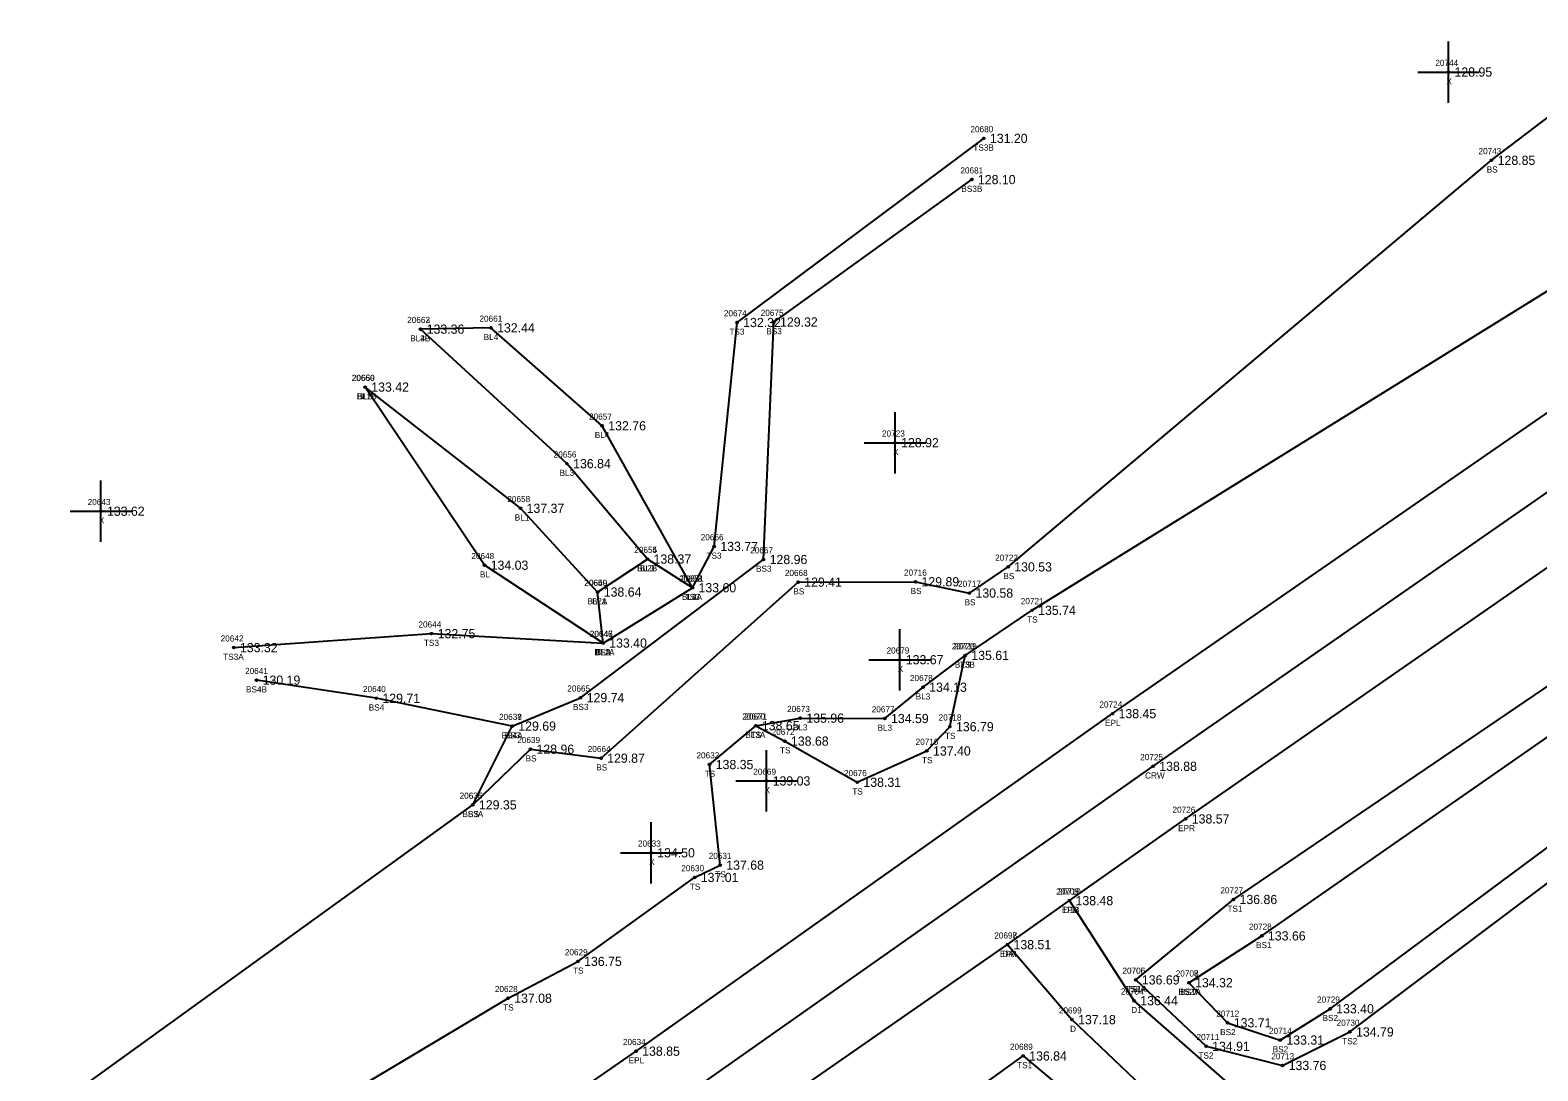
# Model space of a CAD drawing. Extents: x 2449605 to 2452431, y 1012876 to 1014922.
# Drawn here: x 2451655.9 to 2451901.5, y 1014436.4 to 1014606 of the extents above; entities that cross this region are included whole.
import ezdxf

# ---------------------------------------------------------------- set-up
doc = ezdxf.new("R2010")
doc.units = 0
for name, color, linetype in [('RD_DTM_BkLn1', 7, 'Continuous'), ('RD_DTM_BkLn2', 7, 'Continuous'), ('RD_DTM_BkLn_txCode', 7, 'Continuous'), ('RD_EX_Driveway', 7, 'Continuous'), ('RD_EX_Driveway_txCode', 7, 'Continuous'), ('RD_EX_Misc', 7, 'Continuous'), ('RD_EX_Misc_txCode', 7, 'Continuous'), ('RD_EX_Road', 7, 'Continuous'), ('RD_EX_Road_txCode', 7, 'Continuous'), ('RD_EX_TX_Driveway_ELEV', 7, 'Continuous'), ('RD_EX_TX_Misc_ELEV', 7, 'Continuous'), ('RD_EX_TX_Road_ELEV', 7, 'Continuous'), ('RD_HC_Survey_ELEV', 7, 'Continuous'), ('RD_HC_Survey_txCode', 7, 'Continuous'), ('RD_SMD_Locator', 7, 'Continuous')]:
    doc.layers.add(name, color=color, linetype=linetype)

msp = doc.modelspace()

# ---------------------------------------------------------------- linework, layer by layer
at = {"layer": 'RD_DTM_BkLn1'}
msp.add_line((2451748.31, 1014514.42), (2451756.42, 1014519.79), dxfattribs=at)
for points in [[(2451118.89, 1013985.11), (2451203.66, 1014044.04), (2451282.83, 1014099.78), (2451359.44, 1014152.74), (2451440.83, 1014209.36), (2451521.56, 1014265.18), (2451601.57, 1014320.62), (2451681.76, 1014376.26), (2451760.87, 1014431.18), (2451838.81, 1014486.02), (2451917.14, 1014540.46), (2451997.53, 1014596.52), (2452078.1, 1014652.75), (2452159.13, 1014709.2), (2452240.28, 1014765.75), (2452322.88, 1014822.76), (2452350.66, 1014841.92)], [(2451763.75, 1014515.12), (2451749.05, 1014541.51), (2451730.94, 1014557.47), (2451719.46, 1014557.26)], [(2451763.75, 1014515.12), (2451756.42, 1014519.79), (2451743.32, 1014535.34), (2451719.46, 1014557.26)], [(2451749.2, 1014506.11), (2451729.89, 1014518.79), (2451710.44, 1014547.82)], [(2451749.2, 1014506.11), (2451748.31, 1014514.42), (2451735.74, 1014528.07), (2451710.44, 1014547.82)], [(2451774.07, 1014492.64), (2451781.32, 1014493.87), (2451795.11, 1014493.81), (2451801.33, 1014498.91), (2451808.19, 1014504.09)]]:
    msp.add_lwpolyline(points, dxfattribs=at)
at = {"layer": 'RD_DTM_BkLn2'}
for points in [[(2451646.62, 1014421.01), (2451727.98, 1014479.74), (2451737.36, 1014488.81), (2451748.87, 1014487.34), (2451780.97, 1014516.03), (2451800.08, 1014516.09), (2451808.87, 1014514.25), (2451815.19, 1014518.52), (2451893.94, 1014584.77), (2451968.95, 1014641.82), (2452055.92, 1014696.27), (2452133.42, 1014744.91), (2452217.68, 1014799.33), (2452300.38, 1014857.1), (2452325.49, 1014877.68)], [(2451585.42, 1014345.19), (2451660.13, 1014404.28), (2451733.72, 1014448.23), (2451745.11, 1014454.23), (2451764.12, 1014467.91), (2451768.27, 1014469.92), (2451766.55, 1014486.31), (2451774.07, 1014492.64), (2451778.81, 1014490.13), (2451790.61, 1014483.42), (2451801.96, 1014488.52), (2451805.7, 1014492.48), (2451808.19, 1014504.09), (2451819.08, 1014511.44), (2451904.04, 1014564.11), (2451984.51, 1014617.35), (2452065.76, 1014673.28), (2452142.48, 1014732.95), (2452225.73, 1014787.51), (2452309.72, 1014842.9), (2452337.15, 1014861.43)], [(2451835.98, 1014451.22), (2451851.89, 1014464.32), (2451932.21, 1014518.85), (2452011.75, 1014575.42), (2452092.83, 1014631.63), (2452174.74, 1014689.14), (2452254.45, 1014747.21), (2452337.17, 1014802.96), (2452364.31, 1014821.77)], [(2451844.65, 1014450.76), (2451856.52, 1014458.39), (2451935.8, 1014513.56), (2452015.2, 1014570.69), (2452096.12, 1014626.95), (2452178.85, 1014683.69), (2452258.49, 1014741.29), (2452341.42, 1014797.77), (2452367.36, 1014815.99)], [(2451844.65, 1014450.76), (2451850.95, 1014444.22), (2451859.52, 1014441.41), (2451867.64, 1014446.51), (2451943.4, 1014502.76), (2452022.93, 1014557.31), (2452109.2, 1014611.97), (2452189.91, 1014668.61), (2452268.85, 1014723.73), (2452349.37, 1014785.51), (2452374.28, 1014800.27)], [(2451835.98, 1014451.22), (2451847.43, 1014440.4), (2451859.89, 1014437.27), (2451870.87, 1014442.74), (2451946.09, 1014499.37), (2452026.47, 1014553.48), (2452112.39, 1014607.71), (2452192.56, 1014666.03), (2452272.86, 1014720.14), (2452352.28, 1014781.04), (2452376.77, 1014796.76)], [(2451689.04, 1014505.36), (2451721.26, 1014507.64), (2451749.2, 1014506.11), (2451763.75, 1014515.12), (2451767.3, 1014521.85), (2451771.03, 1014558.34), (2451811.23, 1014588.35)], [(2451727.98, 1014479.74), (2451734.39, 1014492.57), (2451745.53, 1014497.2), (2451775.34, 1014519.72), (2451777.03, 1014558.42), (2451809.27, 1014581.63)], [(2451734.39, 1014492.57), (2451712.26, 1014497.11), (2451692.74, 1014500.06)], [(2451122.2, 1013975.67), (2451126.64, 1013971.77), (2451133.91, 1013974.2), (2451213.29, 1014028.58), (2451297.97, 1014080.75), (2451370.59, 1014133.41), (2451455.73, 1014187.81), (2451537.96, 1014241.24), (2451616.44, 1014298.53), (2451698.16, 1014354.19), (2451775.09, 1014408.12), (2451817.62, 1014438.82), (2451833.1, 1014425.86), (2451826.37, 1014414.29)]]:
    msp.add_lwpolyline(points, dxfattribs=at)
at = {"layer": 'RD_EX_Driveway'}
for points in [[(2451893.48, 1014396.37), (2451856.56, 1014429.54), (2451835.71, 1014447.82), (2451825.17, 1014464.13)], [(2451815.07, 1014456.96), (2451825.59, 1014444.74), (2451854.09, 1014417.6), (2451886.88, 1014382.9)]]:
    msp.add_lwpolyline(points, dxfattribs=at)
at = {"layer": 'RD_EX_Misc'}
for p, q in [((2451886.91, 1014594.15), (2451886.91, 1014604.15)), ((2451881.91, 1014599.15), (2451891.91, 1014599.15)), ((2451796.76, 1014533.75), (2451796.76, 1014543.75)), ((2451791.76, 1014538.75), (2451801.76, 1014538.75)), ((2451667.38, 1014522.59), (2451667.38, 1014532.59)), ((2451662.38, 1014527.59), (2451672.38, 1014527.59)), ((2451797.52, 1014498.39), (2451797.52, 1014508.39)), ((2451792.52, 1014503.39), (2451802.52, 1014503.39)), ((2451775.83, 1014478.64), (2451775.83, 1014488.64)), ((2451770.83, 1014483.64), (2451780.83, 1014483.64)), ((2451757.02, 1014466.93), (2451757.02, 1014476.93)), ((2451752.02, 1014471.93), (2451762.02, 1014471.93))]:
    msp.add_line(p, q, dxfattribs=at)
at = {"layer": 'RD_EX_Road'}
for points in [[(2451113.37, 1013993.22), (2451114.95, 1013995.06), (2451198.45, 1014053.46), (2451277.07, 1014108.71), (2451354.65, 1014162.03), (2451438.1, 1014219.98), (2451516.17, 1014274.12), (2451595.76, 1014329.36), (2451675.91, 1014385.09), (2451754.57, 1014439.6), (2451832.18, 1014494.6), (2451911.27, 1014549.31), (2451991.99, 1014605.1), (2452071.96, 1014661.47), (2452153.31, 1014717.5), (2452234.82, 1014774.14), (2452317.24, 1014831.48), (2452344.94, 1014850.58)], [(2451124.98, 1013977.04), (2451208.96, 1014035.6), (2451289.19, 1014091.86), (2451364.64, 1014143.97), (2451446.58, 1014201.16), (2451526.53, 1014256.42), (2451607.39, 1014312.42), (2451687.4, 1014368.14), (2451765.64, 1014422.59), (2451815.07, 1014456.96), (2451825.17, 1014464.13), (2451844.11, 1014477.45), (2451922.22, 1014531.75), (2452002.87, 1014588.1), (2452083.85, 1014644.47), (2452165.65, 1014701.19), (2452246.96, 1014757.82), (2452328.43, 1014814.34), (2452355.9, 1014833.22)]]:
    msp.add_lwpolyline(points, dxfattribs=at)
at = {"layer": 'RD_SMD_Locator'}
for centre in [(2451886.91, 1014599.15), (2451811.23, 1014588.35), (2451893.94, 1014584.77), (2451809.27, 1014581.63), (2451719.46, 1014557.26), (2451719.46, 1014557.26), (2451730.94, 1014557.47), (2451771.03, 1014558.34), (2451777.03, 1014558.42), (2451710.44, 1014547.82), (2451710.44, 1014547.82), (2451749.05, 1014541.51), (2451796.76, 1014538.75), (2451743.32, 1014535.34), (2451667.38, 1014527.59), (2451735.74, 1014528.07), (2451767.3, 1014521.85), (2451729.89, 1014518.79), (2451756.42, 1014519.79), (2451756.42, 1014519.79), (2451775.34, 1014519.72), (2451815.19, 1014518.52), (2451763.75, 1014515.12), (2451763.75, 1014515.12), (2451763.75, 1014515.12), (2451780.97, 1014516.03), (2451800.08, 1014516.09), (2451748.31, 1014514.42), (2451748.31, 1014514.42), (2451808.87, 1014514.25), (2451819.08, 1014511.44), (2451689.04, 1014505.36), (2451721.26, 1014507.64), (2451749.2, 1014506.11), (2451749.2, 1014506.11), (2451749.2, 1014506.11), (2451797.52, 1014503.39), (2451808.19, 1014504.09), (2451808.19, 1014504.09), (2451692.74, 1014500.06), (2451801.33, 1014498.91), (2451712.26, 1014497.11), (2451745.53, 1014497.2), (2451781.32, 1014493.87), (2451795.11, 1014493.81), (2451832.18, 1014494.6), (2451734.39, 1014492.57), (2451734.39, 1014492.57), (2451774.07, 1014492.64), (2451774.07, 1014492.64), (2451805.7, 1014492.48), (2451737.36, 1014488.81), (2451778.81, 1014490.13), (2451801.96, 1014488.52), (2451748.87, 1014487.34), (2451766.55, 1014486.31), (2451838.81, 1014486.02), (2451775.83, 1014483.64), (2451790.61, 1014483.42), (2451727.98, 1014479.74), (2451727.98, 1014479.74), (2451844.11, 1014477.45), (2451757.02, 1014471.93), (2451768.27, 1014469.92), (2451764.12, 1014467.91), (2451825.17, 1014464.13), (2451825.17, 1014464.13), (2451851.89, 1014464.32), (2451815.07, 1014456.96), (2451815.07, 1014456.96), (2451856.52, 1014458.39), (2451745.11, 1014454.23), (2451835.98, 1014451.22), (2451835.98, 1014451.22), (2451844.65, 1014450.76), (2451844.65, 1014450.76), (2451733.72, 1014448.23), (2451835.71, 1014447.82), (2451867.64, 1014446.51), (2451825.59, 1014444.74), (2451850.95, 1014444.22), (2451870.87, 1014442.74), (2451754.57, 1014439.6), (2451847.43, 1014440.4), (2451859.52, 1014441.41), (2451817.62, 1014438.82), (2451859.89, 1014437.27)]:
    msp.add_circle(centre, 0.15, dxfattribs=at)

# ---------------------------------------------------------------- texts
at = {"layer": 'RD_DTM_BkLn_txCode'}
for s, p in [('20680', (2451809.05, 1014589.35)), ('TS3B', (2451809.52, 1014586.35)), ('20743', (2451891.82, 1014585.77)), ('20681', (2451807.41, 1014582.63)), ('BS', (2451893.16, 1014582.77)), ('BS3B', (2451807.57, 1014579.63)), ('20661', (2451729.06, 1014558.47)), ('20674', (2451768.88, 1014559.34)), ('20675', (2451774.88, 1014559.42)), ('20662', (2451717.29, 1014558.26)), ('20663', (2451717.29, 1014558.26)), ('TS3', (2451769.78, 1014556.34)), ('BS3', (2451775.8, 1014556.42)), ('BL3B', (2451717.78, 1014555.26)), ('BL4B', (2451717.78, 1014555.26)), ('BL4', (2451729.74, 1014555.47)), ('20660', (2451708.24, 1014548.82)), ('20659', (2451708.3, 1014548.82)), ('BL1B', (2451709.05, 1014545.82)), ('BLB', (2451709.22, 1014545.82)), ('20657', (2451746.91, 1014542.51)), ('BL4', (2451747.85, 1014539.51)), ('20656', (2451741.15, 1014536.34)), ('BL3', (2451742.11, 1014533.34)), ('20658', (2451733.6, 1014529.07)), ('BL1', (2451734.82, 1014526.07)), ('20666', (2451765.11, 1014522.85)), ('20648', (2451727.74, 1014519.79)), ('20654', (2451754.28, 1014520.79)), ('20655', (2451754.28, 1014520.79)), ('TS3', (2451766.05, 1014519.85)), ('20667', (2451773.17, 1014520.72)), ('20722', (2451813.07, 1014519.52)), ('BL', (2451729.13, 1014516.79)), ('BL2B', (2451754.74, 1014517.79)), ('BL3', (2451755.21, 1014517.79)), ('BS3', (2451774.11, 1014517.72)), ('20668', (2451778.81, 1014517.03)), ('20716', (2451798.22, 1014517.09)), ('20650', (2451746.13, 1014515.42)), ('20649', (2451746.17, 1014515.42)), ('20652', (2451761.6, 1014516.12)), ('20653', (2451761.6, 1014516.12)), ('20651', (2451761.89, 1014516.12)), ('20717', (2451807.04, 1014515.25)), ('BS', (2451814.41, 1014516.52)), ('BL2A', (2451746.62, 1014512.42)), ('BL1', (2451747.39, 1014512.42)), ('BL3A', (2451762.05, 1014513.12)), ('BL4A', (2451762.05, 1014513.12)), ('TS3', (2451762.5, 1014513.12)), ('BS', (2451780.2, 1014514.03)), ('BS', (2451799.3, 1014514.09)), ('BS', (2451808.09, 1014512.25)), ('20721', (2451817.25, 1014512.44)), ('TS', (2451818.29, 1014509.44)), ('20644', (2451719.12, 1014508.64)), ('20646', (2451747.03, 1014507.11)), ('20645', (2451747.06, 1014507.11)), ('20647', (2451747.06, 1014507.11)), ('20642', (2451686.9, 1014506.36)), ('TS3', (2451720.02, 1014505.64)), ('20720', (2451806.03, 1014505.09)), ('20719', (2451806.35, 1014505.09)), ('TS3A', (2451687.31, 1014503.36)), ('BL1A', (2451747.79, 1014504.11)), ('TS3', (2451747.95, 1014504.11)), ('BLA', (2451747.95, 1014504.11)), ('BL3B', (2451806.51, 1014502.09)), ('TS', (2451807.39, 1014502.09)), ('20641', (2451690.88, 1014501.06)), ('20678', (2451799.19, 1014499.91)), ('BS4B', (2451691.03, 1014498.06)), ('20640', (2451710.08, 1014498.11)), ('20665', (2451743.37, 1014498.2)), ('BS4', (2451711.03, 1014495.11)), ('BS3', (2451744.3, 1014495.2)), ('20673', (2451779.18, 1014494.87)), ('20677', (2451792.97, 1014494.81)), ('BL3', (2451800.13, 1014496.91)), ('20637', (2451732.25, 1014493.57)), ('20638', (2451732.25, 1014493.57)), ('20670', (2451771.88, 1014493.64)), ('20671', (2451772.21, 1014493.64)), ('20718', (2451803.87, 1014493.48)), ('BS4A', (2451732.68, 1014490.57)), ('BS3', (2451733.17, 1014490.57)), ('20639', (2451735.22, 1014489.81)), ('BL3A', (2451772.37, 1014490.64)), ('TS', (2451773.27, 1014490.64)), ('20672', (2451776.67, 1014491.13)), ('BL3', (2451780.12, 1014491.87)), ('BL3', (2451793.91, 1014491.81)), ('TS', (2451804.91, 1014490.48)), ('20664', (2451746.7, 1014488.34)), ('20632', (2451764.41, 1014487.31)), ('TS', (2451778.02, 1014488.13)), ('20715', (2451800.12, 1014489.52)), ('BS', (2451736.58, 1014486.81)), ('BS', (2451748.09, 1014485.34)), ('TS', (2451801.16, 1014486.52)), ('TS', (2451765.76, 1014484.31)), ('20676', (2451788.44, 1014484.42)), ('20636', (2451725.82, 1014480.74)), ('20635', (2451725.84, 1014480.74)), ('TS', (2451789.81, 1014481.42)), ('BS3A', (2451726.27, 1014477.74)), ('BS', (2451727.2, 1014477.74)), ('20631', (2451766.41, 1014470.92)), ('20630', (2451761.94, 1014468.91)), ('TS', (2451767.47, 1014467.92)), ('TS', (2451763.33, 1014465.91)), ('20727', (2451849.77, 1014465.32)), ('TS1', (2451850.92, 1014462.32)), ('20728', (2451854.41, 1014459.39)), ('BS1', (2451855.58, 1014456.39)), ('20629', (2451742.97, 1014455.23)), ('TS', (2451744.31, 1014452.23)), ('20706', (2451833.8, 1014452.22)), ('20705', (2451833.82, 1014452.22)), ('20707', (2451842.49, 1014451.76)), ('20708', (2451842.49, 1014451.76)), ('20628', (2451731.57, 1014449.23)), ('TS2A', (2451834.24, 1014449.22)), ('TS1A', (2451834.53, 1014449.22)), ('BS2A', (2451842.93, 1014448.76)), ('BS1A', (2451843.22, 1014448.76)), ('TS', (2451732.92, 1014446.23)), ('20729', (2451865.52, 1014447.51)), ('20712', (2451849.11, 1014445.22)), ('BS2', (2451866.41, 1014444.51)), ('20730', (2451868.71, 1014443.74)), ('20711', (2451845.88, 1014441.4)), ('BS2', (2451849.72, 1014442.22)), ('20714', (2451857.69, 1014442.41)), ('TS2', (2451869.62, 1014440.74)), ('20689', (2451815.48, 1014439.82)), ('TS2', (2451846.19, 1014438.4)), ('20713', (2451858.06, 1014438.27)), ('BS2', (2451858.29, 1014439.41)), ('TS1', (2451816.66, 1014436.82))]:
    msp.add_text(s, height=1, dxfattribs=at).set_placement(p)
at = {"layer": 'RD_EX_Driveway_txCode'}
for s, p in [('20709', (2451823.01, 1014465.13)), ('D1B', (2451824.22, 1014462.13)), ('20698', (2451812.93, 1014457.96)), ('DA', (2451814.28, 1014454.96)), ('20704', (2451833.56, 1014448.82)), ('20699', (2451823.45, 1014445.74)), ('D1', (2451835.24, 1014445.82)), ('D', (2451825.28, 1014442.74))]:
    msp.add_text(s, height=1, dxfattribs=at).set_placement(p)
at = {"layer": 'RD_EX_Misc_txCode'}
for s, p in [('20744', (2451884.79, 1014600.15)), ('X', (2451886.6, 1014597.15)), ('20723', (2451794.64, 1014539.75)), ('X', (2451796.45, 1014536.75)), ('20643', (2451665.23, 1014528.59)), ('X', (2451667.06, 1014525.59)), ('20679', (2451795.38, 1014504.39)), ('X', (2451797.21, 1014501.39)), ('20669', (2451773.66, 1014484.64)), ('X', (2451775.51, 1014481.64)), ('20633', (2451754.88, 1014472.93)), ('X', (2451756.7, 1014469.93))]:
    msp.add_text(s, height=1, dxfattribs=at).set_placement(p)
at = {"layer": 'RD_EX_Road_txCode'}
for s, p in [('20724', (2451830.06, 1014495.6)), ('EPL', (2451830.98, 1014492.6)), ('20726', (2451841.97, 1014478.45)), ('EPR', (2451842.88, 1014475.45)), ('20710', (2451823.29, 1014465.13)), ('EPR', (2451823.94, 1014462.13)), ('20697', (2451812.93, 1014457.96)), ('EPR', (2451813.84, 1014454.96)), ('20634', (2451752.43, 1014440.6)), ('EPL', (2451753.36, 1014437.6))]:
    msp.add_text(s, height=1, dxfattribs=at).set_placement(p)
at = {"layer": 'RD_EX_TX_Driveway_ELEV'}
for s, p in [('138.48', (2451826.17, 1014463.38)), ('138.51', (2451816.07, 1014456.21)), ('136.44', (2451836.71, 1014447.07)), ('137.18', (2451826.59, 1014443.99))]:
    msp.add_text(s, height=1.5, dxfattribs=at).set_placement(p)
at = {"layer": 'RD_EX_TX_Misc_ELEV'}
for s, p in [('128.95', (2451887.91, 1014598.4)), ('131.20', (2451812.23, 1014587.6)), ('128.85', (2451894.94, 1014584.02)), ('128.10', (2451810.27, 1014580.88)), ('133.36', (2451720.46, 1014556.51)), ('133.36', (2451720.46, 1014556.51)), ('132.44', (2451731.94, 1014556.72)), ('132.32', (2451772.03, 1014557.59)), ('129.32', (2451778.03, 1014557.67)), ('133.42', (2451711.44, 1014547.07)), ('133.42', (2451711.44, 1014547.07)), ('132.76', (2451750.05, 1014540.76)), ('128.92', (2451797.76, 1014538)), ('136.84', (2451744.32, 1014534.59)), ('133.62', (2451668.38, 1014526.84)), ('137.37', (2451736.74, 1014527.32)), ('138.37', (2451757.42, 1014519.04)), ('138.37', (2451757.42, 1014519.04)), ('133.77', (2451768.3, 1014521.1)), ('128.96', (2451776.34, 1014518.97)), ('134.03', (2451730.89, 1014518.04)), ('130.53', (2451816.19, 1014517.77)), ('133.60', (2451764.75, 1014514.37)), ('133.60', (2451764.75, 1014514.37)), ('133.60', (2451764.75, 1014514.37)), ('129.41', (2451781.97, 1014515.28)), ('129.89', (2451801.08, 1014515.34)), ('138.64', (2451749.31, 1014513.67)), ('138.64', (2451749.31, 1014513.67)), ('130.58', (2451809.87, 1014513.5)), ('135.74', (2451820.08, 1014510.69)), ('132.75', (2451722.26, 1014506.89)), ('133.32', (2451690.04, 1014504.61)), ('133.40', (2451750.2, 1014505.36)), ('133.40', (2451750.2, 1014505.36)), ('133.40', (2451750.2, 1014505.36)), ('133.67', (2451798.52, 1014502.64)), ('135.61', (2451809.19, 1014503.34)), ('135.61', (2451809.19, 1014503.34)), ('130.19', (2451693.74, 1014499.31)), ('134.13', (2451802.33, 1014498.16)), ('129.71', (2451713.26, 1014496.36)), ('129.74', (2451746.53, 1014496.45)), ('129.69', (2451735.39, 1014491.82)), ('129.69', (2451735.39, 1014491.82)), ('138.65', (2451775.07, 1014491.89)), ('138.65', (2451775.07, 1014491.89)), ('135.96', (2451782.32, 1014493.12)), ('134.59', (2451796.11, 1014493.06)), ('136.79', (2451806.7, 1014491.73)), ('138.68', (2451779.81, 1014489.38)), ('128.96', (2451738.36, 1014488.06)), ('137.40', (2451802.96, 1014487.77)), ('129.87', (2451749.87, 1014486.59)), ('138.35', (2451767.55, 1014485.56)), ('139.03', (2451776.83, 1014482.89)), ('138.31', (2451791.61, 1014482.67)), ('129.35', (2451728.98, 1014478.99)), ('129.35', (2451728.98, 1014478.99)), ('134.50', (2451758.02, 1014471.18)), ('137.01', (2451765.12, 1014467.16)), ('137.68', (2451769.27, 1014469.17)), ('136.86', (2451852.89, 1014463.57)), ('133.66', (2451857.52, 1014457.64)), ('136.75', (2451746.11, 1014453.48)), ('136.69', (2451836.98, 1014450.47)), ('136.69', (2451836.98, 1014450.47)), ('134.32', (2451845.65, 1014450.01)), ('134.32', (2451845.65, 1014450.01)), ('137.08', (2451734.72, 1014447.48)), ('133.40', (2451868.64, 1014445.76)), ('133.71', (2451851.95, 1014443.47)), ('133.31', (2451860.52, 1014440.66)), ('134.79', (2451871.87, 1014441.99)), ('136.84', (2451818.62, 1014438.07)), ('134.91', (2451848.43, 1014439.65)), ('133.76', (2451860.89, 1014436.52))]:
    msp.add_text(s, height=1.5, dxfattribs=at).set_placement(p)
at = {"layer": 'RD_EX_TX_Road_ELEV'}
for s, p in [('138.45', (2451833.18, 1014493.85)), ('138.57', (2451845.11, 1014476.7)), ('138.48', (2451826.17, 1014463.38)), ('138.51', (2451816.07, 1014456.21)), ('138.85', (2451755.57, 1014438.85))]:
    msp.add_text(s, height=1.5, dxfattribs=at).set_placement(p)
at = {"layer": 'RD_HC_Survey_ELEV'}
msp.add_text('138.88', height=1.5, dxfattribs=at).set_placement((2451839.81, 1014485.27))
at = {"layer": 'RD_HC_Survey_txCode'}
for s, p in [('20725', (2451836.7, 1014487.02)), ('CRW', (2451837.5, 1014484.02))]:
    msp.add_text(s, height=1, dxfattribs=at).set_placement(p)

doc.saveas('drawing.dxf')
